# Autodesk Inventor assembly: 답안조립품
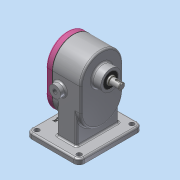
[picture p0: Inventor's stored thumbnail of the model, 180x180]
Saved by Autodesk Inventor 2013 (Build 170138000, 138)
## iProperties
Created: 2020-09
Part Number: 답안조립품
Document SubType Name: Assembly
Designer: Administrator
Author: Administrator
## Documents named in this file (11)
- C:\Users\Administrator\Desktop\700906V1008\답안조립품.iam
- C:\Users\Administrator\Desktop\700906V1008\본체.ipt
- C:\Users\Administrator\Desktop\700906V1008\베어링부시.ipt
- C:\Users\Administrator\Desktop\700906V1008\개스킷.ipt
- C:\Users\Administrator\Desktop\700906V1008\커버.ipt
- C:\Users\Administrator\Desktop\700906V1008\볼트 M5.ipt
- C:\Users\Administrator\Desktop\700906V1008\메인축.ipt
- C:\Users\Administrator\Desktop\700906V1008\서브축.ipt
- C:\Users\Administrator\Desktop\700906V1008\키 6 x 6 x 18.ipt
- C:\Users\Administrator\Desktop\700906V1008\오일 실 16 28 7.ipt
- C:\Users\Administrator\Desktop\700906V1008\스퍼기어.ipt
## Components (1 placed, 1 different names)
1. 개스킷:1
